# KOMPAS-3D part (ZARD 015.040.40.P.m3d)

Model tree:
1. Плоскость XY
2. Плоскость ZX
3. Плоскость ZY
4. Ось X
5. Ось Y
6. Ось Z
7. Начало координат
8. Смещенная плоскость:2
     Расстояние = 57.5
9. Булева операция:3
10. Булева операция:4

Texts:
  Сталь 20 ГОСТ 1050-88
